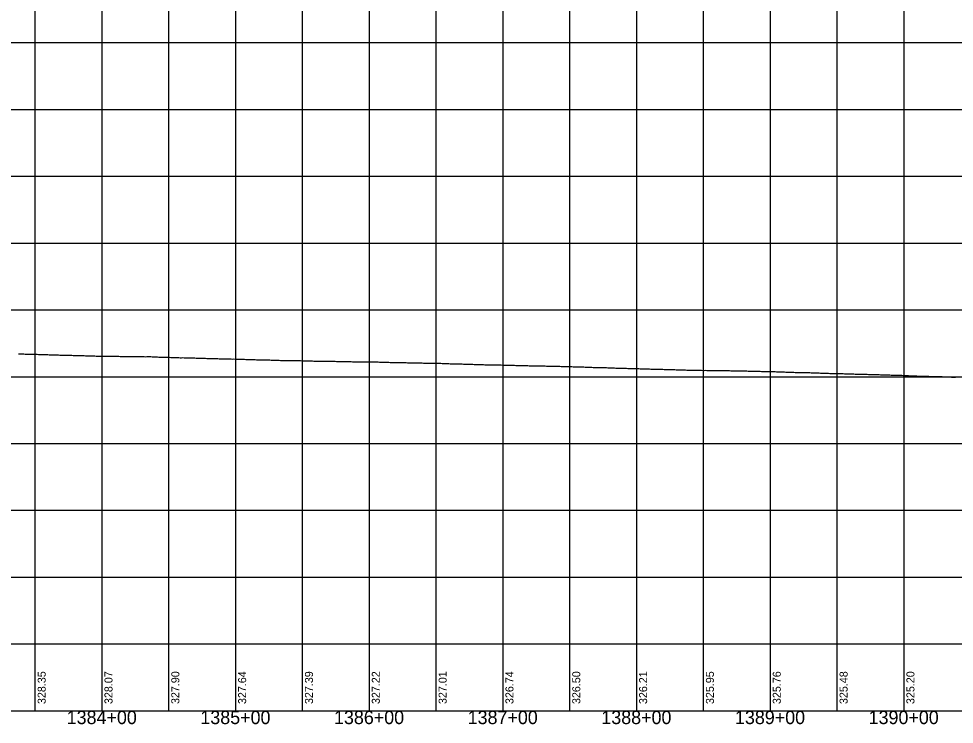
# Model space of a CAD drawing. Extents: x -90830 to 2015517, y -20856 to 836331.
# Drawn here: x 10361 to 11061, y 20053 to 20581 of the extents above; entities that cross this region are included whole.
import ezdxf

# ---------------------------------------------------------------- set-up
doc = ezdxf.new("R2010")
doc.units = 0
for name, color, linetype in [('Level 1', 7, 'Continuous'), ('RD_DDB_Profile_EX', 7, 'Continuous'), ('RD_DDB_StaTX', 7, 'Continuous'), ('RD_DDB_StripGrade', 7, 'Continuous'), ('RD_GPK_Profile_Cell', 7, 'Continuous')]:
    doc.layers.add(name, color=color, linetype=linetype)

msp = doc.modelspace()

# ---------------------------------------------------------------- linework, layer by layer
at = {"layer": 'Level 1'}
for p, q in [((10373.46, 21062.87), (10373.46, 20562.87)), ((10423.46, 21062.87), (10423.46, 20562.87)), ((10473.46, 21062.87), (10473.46, 20562.87)), ((10523.46, 21062.87), (10523.46, 20562.87)), ((10573.46, 21062.87), (10573.46, 20562.87)), ((10623.46, 21062.87), (10623.46, 20562.87)), ((10673.46, 21062.87), (10673.46, 20562.87)), ((10723.46, 21062.87), (10723.46, 20562.87)), ((10773.46, 21062.87), (10773.46, 20562.87)), ((10823.46, 21062.87), (10823.46, 20562.87)), ((10873.46, 21062.87), (10873.46, 20562.87)), ((10923.46, 21062.87), (10923.46, 20562.87)), ((10973.46, 21062.87), (10973.46, 20562.87)), ((11023.46, 21062.87), (11023.46, 20562.87)), ((9623.46, 20562.87), (11223.46, 20562.87)), ((9623.46, 20562.87), (11223.46, 20562.87)), ((10373.46, 20562.87), (10373.46, 20062.87)), ((10423.46, 20562.87), (10423.46, 20062.87)), ((10473.46, 20562.87), (10473.46, 20062.87)), ((10523.46, 20562.87), (10523.46, 20062.87)), ((10573.46, 20562.87), (10573.46, 20062.87)), ((10623.46, 20562.87), (10623.46, 20062.87)), ((10673.46, 20562.87), (10673.46, 20062.87)), ((10723.46, 20562.87), (10723.46, 20062.87)), ((10773.46, 20562.87), (10773.46, 20062.87)), ((10823.46, 20562.87), (10823.46, 20062.87)), ((10873.46, 20562.87), (10873.46, 20062.87)), ((10923.46, 20562.87), (10923.46, 20062.87)), ((10973.46, 20562.87), (10973.46, 20062.87)), ((11023.46, 20562.87), (11023.46, 20062.87)), ((9623.46, 20512.87), (11223.46, 20512.87)), ((9623.46, 20462.87), (11223.46, 20462.87)), ((9623.46, 20412.87), (11223.46, 20412.87)), ((9623.46, 20362.87), (11223.46, 20362.87)), ((9623.46, 20312.87), (11223.46, 20312.87)), ((9623.46, 20262.87), (11223.46, 20262.87)), ((9623.46, 20212.87), (11223.46, 20212.87)), ((9623.46, 20162.87), (11223.46, 20162.87)), ((9623.46, 20112.87), (11223.46, 20112.87)), ((9623.46, 20062.87), (11223.46, 20062.87))]:
    msp.add_line(p, q, dxfattribs=at)
at = {"layer": 'RD_DDB_Profile_EX'}
for points in [[(10361.15, 20329.97), (10362.15, 20329.95), (10363.15, 20329.97), (10364.15, 20329.91), (10365.15, 20329.84), (10366.15, 20329.82), (10367.15, 20329.77), (10368.15, 20329.75), (10369.15, 20329.77), (10370.15, 20329.71), (10371.15, 20329.64), (10372.15, 20329.64), (10373.15, 20329.64), (10374.15, 20329.64), (10375.15, 20329.62), (10376.15, 20329.56), (10377.15, 20329.47), (10378.15, 20329.4), (10379.15, 20329.4), (10380.15, 20329.4), (10381.15, 20329.41), (10382.15, 20329.43), (10383.15, 20329.38), (10384.15, 20329.32), (10385.15, 20329.25), (10386.15, 20329.25), (10387.15, 20329.24), (10388.15, 20329.19), (10389.15, 20329.15), (10390.15, 20329.15), (10391.15, 20329.13), (10392.15, 20329.06), (10393.15, 20329.04), (10394.15, 20329), (10395.15, 20329), (10396.15, 20329), (10397.15, 20328.98), (10398.15, 20328.93), (10399.15, 20328.87), (10400.15, 20328.9), (10401.15, 20328.87), (10402.15, 20328.79), (10403.15, 20328.75), (10404.15, 20328.74), (10405.15, 20328.69), (10406.15, 20328.66), (10407.15, 20328.64), (10408.15, 20328.61), (10409.15, 20328.61), (10410.15, 20328.6), (10411.15, 20328.58), (10412.15, 20328.55), (10413.15, 20328.55), (10414.15, 20328.55), (10415.15, 20328.53), (10416.15, 20328.48), (10417.15, 20328.43), (10418.15, 20328.38), (10419.15, 20328.34), (10420.15, 20328.31), (10421.15, 20328.29), (10422.15, 20328.26), (10423.15, 20328.24), (10424.15, 20328.21), (10425.15, 20328.23), (10426.15, 20328.3), (10427.15, 20328.28), (10428.15, 20328.24), (10429.15, 20328.2), (10430.15, 20328.21), (10431.15, 20328.19), (10432.15, 20328.14), (10433.15, 20328.11), (10434.15, 20328.11), (10435.15, 20328.15), (10436.15, 20328.14), (10437.15, 20328.09), (10438.15, 20328.05), (10439.15, 20328.05), (10440.15, 20328.05), (10441.15, 20328.05), (10442.15, 20328.08), (10443.15, 20328.02), (10444.15, 20327.96)], [(10444.15, 20327.96), (10445.15, 20327.98), (10446.15, 20327.97), (10447.15, 20327.93), (10448.15, 20327.94), (10449.15, 20327.97), (10450.15, 20327.96), (10451.15, 20327.93), (10452.15, 20327.93), (10453.15, 20327.92), (10454.15, 20327.88), (10455.15, 20327.87), (10456.15, 20327.84), (10457.15, 20327.87), (10458.15, 20327.87), (10459.15, 20327.87), (10460.15, 20327.85), (10461.15, 20327.8), (10462.15, 20327.75), (10463.15, 20327.7), (10464.15, 20327.63), (10465.15, 20327.62), (10466.15, 20327.57), (10467.15, 20327.57), (10468.15, 20327.56), (10469.15, 20327.51), (10470.15, 20327.48), (10471.15, 20327.46), (10472.15, 20327.41), (10473.15, 20327.38), (10474.15, 20327.36), (10475.15, 20327.33), (10476.15, 20327.33), (10477.15, 20327.33), (10478.15, 20327.32), (10479.15, 20327.26), (10480.15, 20327.23), (10481.15, 20327.2), (10482.15, 20327.09), (10483.15, 20327.09), (10484.15, 20327.12), (10485.15, 20327.06), (10486.15, 20326.99), (10487.15, 20326.99), (10488.15, 20327.01), (10489.15, 20326.95), (10490.15, 20326.88), (10491.15, 20326.88), (10492.15, 20326.87), (10493.15, 20326.86), (10494.15, 20326.81), (10495.15, 20326.78), (10496.15, 20326.76), (10497.15, 20326.72), (10498.15, 20326.71), (10499.15, 20326.67), (10500.15, 20326.66), (10501.15, 20326.62), (10502.15, 20326.57), (10503.15, 20326.53), (10504.15, 20326.51), (10505.15, 20326.46), (10506.15, 20326.43), (10507.15, 20326.42), (10508.15, 20326.38), (10509.15, 20326.37), (10510.15, 20326.36), (10511.15, 20326.33), (10512.15, 20326.32), (10513.15, 20326.29), (10514.15, 20326.21), (10515.15, 20326.18), (10516.15, 20326.18), (10517.15, 20326.17), (10518.15, 20326.17), (10519.15, 20326.17), (10520.15, 20326.14), (10521.15, 20326.08), (10522.15, 20326.11), (10523.15, 20326.09), (10524.15, 20326.01), (10525.15, 20326), (10526.15, 20326), (10527.15, 20326), (10528.15, 20325.99), (10529.15, 20325.94), (10530.15, 20325.88), (10531.15, 20325.81), (10532.15, 20325.82), (10533.15, 20325.84), (10534.15, 20325.79), (10535.15, 20325.71), (10536.15, 20325.69), (10537.15, 20325.64), (10538.15, 20325.63), (10539.15, 20325.59), (10540.15, 20325.58), (10541.15, 20325.53), (10542.15, 20325.5), (10543.15, 20325.53), (10544.15, 20325.53)], [(10544.15, 20325.53), (10545.15, 20325.48), (10546.15, 20325.47), (10547.15, 20325.43), (10548.15, 20325.42), (10549.15, 20325.37), (10550.15, 20325.28), (10551.15, 20325.28), (10552.15, 20325.28), (10553.15, 20325.27), (10554.15, 20325.19), (10555.15, 20325.17), (10556.15, 20325.12), (10557.15, 20325.04), (10558.15, 20325.04), (10559.15, 20325.03), (10560.15, 20325), (10561.15, 20325.04), (10562.15, 20325.04), (10563.15, 20325.04), (10564.15, 20325.04), (10565.15, 20325.03), (10566.15, 20324.98), (10567.15, 20324.94), (10568.15, 20324.93), (10569.15, 20324.89), (10570.15, 20324.89), (10571.15, 20324.89), (10572.15, 20324.88), (10573.15, 20324.84), (10574.15, 20324.84), (10575.15, 20324.83), (10576.15, 20324.79), (10577.15, 20324.78), (10578.15, 20324.73), (10579.15, 20324.7), (10580.15, 20324.68), (10581.15, 20324.63), (10582.15, 20324.6), (10583.15, 20324.6), (10584.15, 20324.6), (10585.15, 20324.59), (10586.15, 20324.56), (10587.15, 20324.55), (10588.15, 20324.56), (10589.15, 20324.56), (10590.15, 20324.55), (10591.15, 20324.56), (10592.15, 20324.54), (10593.15, 20324.5), (10594.15, 20324.46), (10595.15, 20324.45), (10596.15, 20324.41), (10597.15, 20324.4), (10598.15, 20324.36), (10599.15, 20324.35), (10600.15, 20324.33), (10601.15, 20324.35), (10602.15, 20324.32), (10603.15, 20324.32), (10604.15, 20324.3), (10605.15, 20324.27), (10606.15, 20324.24), (10607.15, 20324.17), (10608.15, 20324.16), (10609.15, 20324.12), (10610.15, 20324.11), (10611.15, 20324.07), (10612.15, 20324.07), (10613.15, 20324.06), (10614.15, 20324.02), (10615.15, 20324.02), (10616.15, 20324.02), (10617.15, 20324.02), (10618.15, 20324.02), (10619.15, 20324.01), (10620.15, 20323.97), (10621.15, 20323.99), (10622.15, 20324.01), (10623.15, 20323.97), (10624.15, 20323.96), (10625.15, 20323.94), (10626.15, 20323.97), (10627.15, 20323.96), (10628.15, 20323.91), (10629.15, 20323.87), (10630.15, 20323.86), (10631.15, 20323.82), (10632.15, 20323.82), (10633.15, 20323.82), (10634.15, 20323.81), (10635.15, 20323.76), (10636.15, 20323.7), (10637.15, 20323.62), (10638.15, 20323.61), (10639.15, 20323.56), (10640.15, 20323.52), (10641.15, 20323.52), (10642.15, 20323.52), (10643.15, 20323.51), (10644.15, 20323.47)], [(10644.15, 20323.47), (10645.15, 20323.46), (10646.15, 20323.44), (10647.15, 20323.46), (10648.15, 20323.42), (10649.15, 20323.42), (10650.15, 20323.41), (10651.15, 20323.36), (10652.15, 20323.32), (10653.15, 20323.32), (10654.15, 20323.32), (10655.15, 20323.3), (10656.15, 20323.22), (10657.15, 20323.24), (10658.15, 20323.26), (10659.15, 20323.22), (10660.15, 20323.22), (10661.15, 20323.22), (10662.15, 20323.22), (10663.15, 20323.19), (10664.15, 20323.09), (10665.15, 20323.02), (10666.15, 20323.04), (10667.15, 20323.06), (10668.15, 20323.02), (10669.15, 20323.02), (10670.15, 20323.01), (10671.15, 20322.97), (10672.15, 20322.96), (10673.15, 20322.92), (10674.15, 20322.92), (10675.15, 20322.92), (10676.15, 20322.91), (10677.15, 20322.86), (10678.15, 20322.81), (10679.15, 20322.77), (10680.15, 20322.76), (10681.15, 20322.71), (10682.15, 20322.67), (10683.15, 20322.66), (10684.15, 20322.6), (10685.15, 20322.55), (10686.15, 20322.53), (10687.15, 20322.57), (10688.15, 20322.57), (10689.15, 20322.55), (10690.15, 20322.49), (10691.15, 20322.4), (10692.15, 20322.37), (10693.15, 20322.37), (10694.15, 20322.35), (10695.15, 20322.3), (10696.15, 20322.25), (10697.15, 20322.21), (10698.15, 20322.18), (10699.15, 20322.11), (10700.15, 20322.13), (10701.15, 20322.15), (10702.15, 20322.1), (10703.15, 20322.06), (10704.15, 20322.06), (10705.15, 20322.05), (10706.15, 20322), (10707.15, 20321.95), (10708.15, 20321.91), (10709.15, 20321.9), (10710.15, 20321.85), (10711.15, 20321.81), (10712.15, 20321.81), (10713.15, 20321.79), (10714.15, 20321.76), (10715.15, 20321.73), (10716.15, 20321.65), (10717.15, 20321.62), (10718.15, 20321.66), (10719.15, 20321.66), (10720.15, 20321.64), (10721.15, 20321.61), (10722.15, 20321.61), (10723.15, 20321.59), (10724.15, 20321.56), (10725.15, 20321.56), (10726.15, 20321.55), (10727.15, 20321.52), (10728.15, 20321.55), (10729.15, 20321.48), (10730.15, 20321.41), (10731.15, 20321.4), (10732.15, 20321.37), (10733.15, 20321.35), (10734.15, 20321.3), (10735.15, 20321.27), (10736.15, 20321.27), (10737.15, 20321.27), (10738.15, 20321.26), (10739.15, 20321.21), (10740.15, 20321.17), (10741.15, 20321.17), (10742.15, 20321.15), (10743.15, 20321.06), (10744.15, 20321.02)], [(10744.15, 20321.02), (10745.15, 20321.03), (10746.15, 20321.03), (10747.15, 20321.01), (10748.15, 20320.96), (10749.15, 20320.94), (10750.15, 20320.98), (10751.15, 20320.98), (10752.15, 20320.96), (10753.15, 20320.93), (10754.15, 20320.91), (10755.15, 20320.86), (10756.15, 20320.82), (10757.15, 20320.78), (10758.15, 20320.77), (10759.15, 20320.73), (10760.15, 20320.73), (10761.15, 20320.73), (10762.15, 20320.72), (10763.15, 20320.66), (10764.15, 20320.63), (10765.15, 20320.63), (10766.15, 20320.61), (10767.15, 20320.56), (10768.15, 20320.51), (10769.15, 20320.48), (10770.15, 20320.48), (10771.15, 20320.46), (10772.15, 20320.41), (10773.15, 20320.38), (10774.15, 20320.39), (10775.15, 20320.41), (10776.15, 20320.36), (10777.15, 20320.31), (10778.15, 20320.26), (10779.15, 20320.22), (10780.15, 20320.22), (10781.15, 20320.22), (10782.15, 20320.22), (10783.15, 20320.2), (10784.15, 20320.14), (10785.15, 20320.05), (10786.15, 20320.02), (10787.15, 20319.98), (10788.15, 20319.91), (10789.15, 20319.91), (10790.15, 20319.9), (10791.15, 20319.85), (10792.15, 20319.81), (10793.15, 20319.8), (10794.15, 20319.76), (10795.15, 20319.77), (10796.15, 20319.78), (10797.15, 20319.69), (10798.15, 20319.66), (10799.15, 20319.67), (10800.15, 20319.71), (10801.15, 20319.68), (10802.15, 20319.59), (10803.15, 20319.54), (10804.15, 20319.49), (10805.15, 20319.45), (10806.15, 20319.44), (10807.15, 20319.39), (10808.15, 20319.35), (10809.15, 20319.35), (10810.15, 20319.32), (10811.15, 20319.25), (10812.15, 20319.23), (10813.15, 20319.2), (10814.15, 20319.2), (10815.15, 20319.18), (10816.15, 20319.12), (10817.15, 20319.05), (10818.15, 20319.04), (10819.15, 20319.05), (10820.15, 20319.05), (10821.15, 20319.02), (10822.15, 20318.95), (10823.15, 20318.94), (10824.15, 20318.9), (10825.15, 20318.89), (10826.15, 20318.84), (10827.15, 20318.8), (10828.15, 20318.79), (10829.15, 20318.76), (10830.15, 20318.74), (10831.15, 20318.69), (10832.15, 20318.66), (10833.15, 20318.65), (10834.15, 20318.6), (10835.15, 20318.56), (10836.15, 20318.56), (10837.15, 20318.55), (10838.15, 20318.5), (10839.15, 20318.47), (10840.15, 20318.47), (10841.15, 20318.47), (10842.15, 20318.46), (10843.15, 20318.39), (10844.15, 20318.32)], [(10844.15, 20318.32), (10845.15, 20318.31), (10846.15, 20318.26), (10847.15, 20318.22), (10848.15, 20318.24), (10849.15, 20318.28), (10850.15, 20318.25), (10851.15, 20318.18), (10852.15, 20318.16), (10853.15, 20318.11), (10854.15, 20318.08), (10855.15, 20318.08), (10856.15, 20318.07), (10857.15, 20318.02), (10858.15, 20317.97), (10859.15, 20317.92), (10860.15, 20317.88), (10861.15, 20317.86), (10862.15, 20317.79), (10863.15, 20317.8), (10864.15, 20317.84), (10865.15, 20317.84), (10866.15, 20317.82), (10867.15, 20317.77), (10868.15, 20317.73), (10869.15, 20317.68), (10870.15, 20317.64), (10871.15, 20317.64), (10872.15, 20317.63), (10873.15, 20317.6), (10874.15, 20317.61), (10875.15, 20317.63), (10876.15, 20317.6), (10877.15, 20317.6), (10878.15, 20317.59), (10879.15, 20317.55), (10880.15, 20317.57), (10881.15, 20317.6), (10882.15, 20317.59), (10883.15, 20317.56), (10884.15, 20317.55), (10885.15, 20317.51), (10886.15, 20317.51), (10887.15, 20317.5), (10888.15, 20317.47), (10889.15, 20317.47), (10890.15, 20317.47), (10891.15, 20317.47), (10892.15, 20317.46), (10893.15, 20317.4), (10894.15, 20317.32), (10895.15, 20317.3), (10896.15, 20317.34), (10897.15, 20317.32), (10898.15, 20317.29), (10899.15, 20317.29), (10900.15, 20317.3), (10901.15, 20317.28), (10902.15, 20317.23), (10903.15, 20317.2), (10904.15, 20317.19), (10905.15, 20317.15), (10906.15, 20317.14), (10907.15, 20317.11), (10908.15, 20317.1), (10909.15, 20317.05), (10910.15, 20317.01), (10911.15, 20317.01), (10912.15, 20317.01), (10913.15, 20317), (10914.15, 20316.97), (10915.15, 20316.97), (10916.15, 20316.94), (10917.15, 20316.86), (10918.15, 20316.82), (10919.15, 20316.82), (10920.15, 20316.8), (10921.15, 20316.77), (10922.15, 20316.75), (10923.15, 20316.7), (10924.15, 20316.67), (10925.15, 20316.66), (10926.15, 20316.63), (10927.15, 20316.62), (10928.15, 20316.58), (10929.15, 20316.57), (10930.15, 20316.54), (10931.15, 20316.53), (10932.15, 20316.49), (10933.15, 20316.47), (10934.15, 20316.39), (10935.15, 20316.35), (10936.15, 20316.35), (10937.15, 20316.33), (10938.15, 20316.24), (10939.15, 20316.19), (10940.15, 20316.17), (10941.15, 20316.18), (10942.15, 20316.11), (10943.15, 20316.11), (10944.15, 20316.08)], [(10944.15, 20316.08), (10945.15, 20315.99), (10946.15, 20315.96), (10947.15, 20315.95), (10948.15, 20315.9), (10949.15, 20315.87), (10950.15, 20315.87), (10951.15, 20315.88), (10952.15, 20315.88), (10953.15, 20315.87), (10954.15, 20315.83), (10955.15, 20315.84), (10956.15, 20315.83), (10957.15, 20315.79), (10958.15, 20315.76), (10959.15, 20315.69), (10960.15, 20315.65), (10961.15, 20315.54), (10962.15, 20315.5), (10963.15, 20315.5), (10964.15, 20315.5), (10965.15, 20315.48), (10966.15, 20315.43), (10967.15, 20315.39), (10968.15, 20315.35), (10969.15, 20315.35), (10970.15, 20315.32), (10971.15, 20315.25), (10972.15, 20315.25), (10973.15, 20315.25), (10974.15, 20315.26), (10975.15, 20315.24), (10976.15, 20315.21), (10977.15, 20315.21), (10978.15, 20315.18), (10979.15, 20315.11), (10980.15, 20315.1), (10981.15, 20315.03), (10982.15, 20314.96), (10983.15, 20314.95), (10984.15, 20314.91), (10985.15, 20314.91), (10986.15, 20314.88), (10987.15, 20314.8), (10988.15, 20314.78), (10989.15, 20314.75), (10990.15, 20314.75), (10991.15, 20314.73), (10992.15, 20314.7), (10993.15, 20314.71), (10994.15, 20314.66), (10995.15, 20314.63), (10996.15, 20314.63), (10997.15, 20314.61), (10998.15, 20314.58), (10999.15, 20314.58), (11000.15, 20314.57), (11001.15, 20314.52), (11002.15, 20314.48), (11003.15, 20314.49), (11004.15, 20314.52), (11005.15, 20314.46), (11006.15, 20314.36), (11007.15, 20314.29), (11008.15, 20314.28), (11009.15, 20314.27), (11010.15, 20314.22), (11011.15, 20314.17), (11012.15, 20314.14), (11013.15, 20314.16), (11014.15, 20314.1), (11015.15, 20314.02), (11016.15, 20314.02), (11017.15, 20314.01), (11018.15, 20313.97), (11019.15, 20313.96), (11020.15, 20313.93), (11021.15, 20313.93), (11022.15, 20313.92), (11023.15, 20313.87), (11024.15, 20313.82), (11025.15, 20313.77), (11026.15, 20313.73), (11027.15, 20313.68), (11028.15, 20313.62), (11029.15, 20313.53), (11030.15, 20313.47), (11031.15, 20313.39), (11032.15, 20313.39), (11033.15, 20313.39), (11034.15, 20313.37), (11035.15, 20313.32), (11036.15, 20313.29), (11037.15, 20313.32), (11038.15, 20313.32), (11039.15, 20313.33), (11040.15, 20313.35), (11041.15, 20313.28), (11042.15, 20313.15), (11043.15, 20313.12), (11044.15, 20313.12)], [(11044.15, 20313.12), (11045.15, 20313.1), (11046.15, 20313.05), (11047.15, 20312.97), (11048.15, 20312.96), (11049.15, 20312.91), (11050.15, 20312.88), (11051.15, 20312.92), (11052.15, 20312.9), (11053.15, 20312.84), (11054.15, 20312.75), (11055.15, 20312.71), (11056.15, 20312.71), (11057.15, 20312.69), (11058.15, 20312.63), (11059.15, 20312.55), (11060.15, 20312.56), (11061.15, 20312.59), (11062.15, 20312.58)]]:
    msp.add_lwpolyline(points, dxfattribs=at)
at = {"layer": 'RD_GPK_Profile_Cell'}
msp.add_line((9644.15, 20062.87), (12444.15, 20062.87), dxfattribs=at)

# ---------------------------------------------------------------- texts
at = {"layer": 'RD_DDB_StaTX'}
for s, p in [('1384+00', (10397.21, 20052.87)), ('1385+00', (10497.21, 20052.87)), ('1386+00', (10597.21, 20052.87)), ('1387+00', (10697.21, 20052.87)), ('1388+00', (10797.21, 20052.87)), ('1389+00', (10897.21, 20052.87)), ('1390+00', (10997.21, 20052.87))]:
    msp.add_text(s, height=10, dxfattribs=at).set_placement(p)
at = {"layer": 'RD_DDB_StripGrade'}
for s, p in [('328.35', (10381.46, 20067.87)), ('328.07', (10431.46, 20067.87)), ('327.90', (10481.46, 20067.87)), ('327.64', (10531.46, 20067.87)), ('327.39', (10581.46, 20067.87)), ('327.22', (10631.46, 20067.87)), ('327.01', (10681.46, 20067.87)), ('326.74', (10731.46, 20067.87)), ('326.50', (10781.46, 20067.87)), ('326.21', (10831.46, 20067.87)), ('325.95', (10881.46, 20067.87)), ('325.76', (10931.46, 20067.87)), ('325.48', (10981.46, 20067.87)), ('325.20', (11031.46, 20067.87))]:
    msp.add_text(s, height=6, rotation=90, dxfattribs=at).set_placement(p)

doc.saveas('drawing.dxf')
